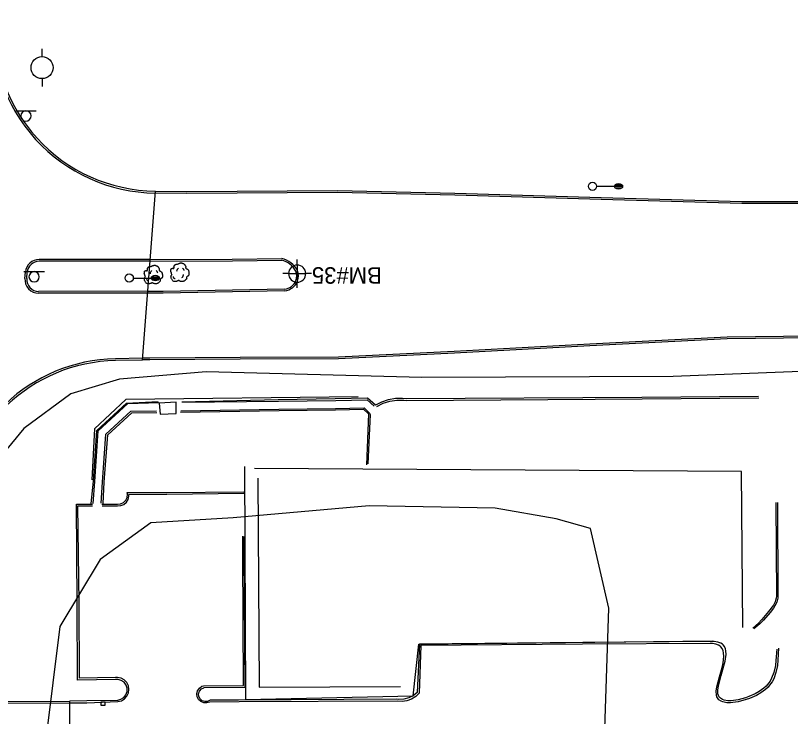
# Model space of a CAD drawing. Extents: x 2145380 to 2157287, y 139568 to 149130.
# Drawn here: x 2151088.5 to 2151370.7, y 140820 to 141075.2 of the extents above; entities that cross this region are included whole.
import ezdxf

# ---------------------------------------------------------------- set-up
doc = ezdxf.new("R2010")
doc.units = 0
for name, color, linetype in [('PR_PREVIOUSLY CONSTRUCTED', 7, 'Continuous'), ('SURV_Benchmark', 7, 'Continuous'), ('TOPO_Building', 7, 'Continuous'), ('TOPO_Curb Back', 7, 'Continuous'), ('TOPO_DRAIN Storm Sewer', 7, 'Continuous'), ('TOPO_Light Pole', 7, 'Continuous'), ('TOPO_Power Pole', 7, 'Continuous'), ('TOPO_Sign', 7, 'Continuous'), ('TOPO_Tree', 7, 'Continuous')]:
    doc.layers.add(name, color=color, linetype=linetype)

# ---------------------------------------------------------------- blocks, each defined once
blk = doc.blocks.new('LP')
at = {"layer": 'TOPO_Light Pole'}
blk.add_line((3.81, 0), (20.32, 0), dxfattribs=at)
for points in [[(20.32, 0), (27.94, 0)], [(20.32, 0), (23.5, 0)], [(20.83, 1.27), (27.43, 1.27)], [(20.83, 1.27), (23.5, 1.27)], [(23.71, 1.27), (27.43, 1.27)], [(23.71, 0), (27.94, 0)], [(20.83, -1.27), (27.43, -1.27)], [(20.83, -1.27), (23.5, -1.27)], [(23.71, -1.27), (27.43, -1.27)]]:
    blk.add_lwpolyline(points, dxfattribs=at)
blk.add_circle((0, 0), 3.81, dxfattribs=at)
blk.add_ellipse((24.13, 0), major_axis=(3.81, 0), ratio=0.666667, dxfattribs=at)
blk = doc.blocks.new('TREE')
at = {"layer": 'TOPO_Tree'}
for points in [[(-14.1, -0.4), (-14.2, 0.5), (-14.4, 1.4), (-14.6, 2.3), (-14.8, 3.2), (-15.5, 4), (-15.7, 4.9), (-15.8, 5.6), (-15.7, 6.3), (-15.7, 7), (-15.6, 7.9), (-15.7, 8.8), (-15.1, 9.7), (-14.6, 10.4), (-13.8, 10.5), (-13, 10.7), (-12.2, 11), (-11.1, 10), (-10.4, 10.7), (-9.4, 11.7), (-10.3, 13.3), (-9.8, 14.4), (-9.6, 15.1), (-9.3, 15.9), (-8.8, 16.5), (-8.2, 17.3), (-7.5, 17.7), (-6.7, 18.1), (-6.1, 18.4), (-5.6, 18.6), (-5.1, 18.7), (-4.5, 18.7), (-4, 18.5), (-3.5, 18.1)], [(-3.5, 17.6), (-3.1, 18.3), (-2.6, 18.8), (-1.9, 19.2), (-1, 19.7), (-0.2, 20), (0.7, 20.2), (1.6, 20.5), (2.5, 20.8), (3.4, 20.8), (4.1, 20.7), (4.8, 20.5), (5.5, 20.2), (6.4, 19.9), (7.3, 19.7), (8.2, 19.2), (9.4, 18.4), (10, 17.2), (10.8, 16), (11.2, 15.3), (11.6, 14.6), (11.9, 13.9), (12.2, 13.1), (11.4, 12), (11.9, 11.2), (12, 11), (12.2, 10.9), (12.4, 10.7), (12.9, 10.4), (13.5, 10), (14, 9.7), (14.7, 9.2), (15.4, 8.7), (16.1, 8.1), (16.7, 7.5), (16.9, 6.7), (17.1, 6), (17.6, 4.4), (17.7, 2.8), (17.7, 1.2), (17.7, -0.2), (17.8, -2.2), (16.6, -3), (15.5, -3.8), (14.3, -4.6), (13.2, -5.3)], [(13.2, -5.3), (13.3, -5.8), (13.4, -6.3), (13.4, -6.7), (13.8, -8.5), (12.2, -10), (10.8, -11.5), (10, -12.3), (9.1, -12.8), (8.2, -13.1), (6, -13.8), (3.3, -13.6), (1.3, -13.1), (0.5, -12.9), (-0.1, -11.4), (-0.8, -11.5), (-2, -11.6), (-3.3, -12.8), (-4.5, -13.1), (-6.1, -13.5), (-7.8, -14), (-9.3, -13.6), (-11.4, -13.1), (-12.8, -11.4), (-14.1, -9.4), (-15.3, -7.3), (-15.6, -5.1), (-15.1, -3), (-14.9, -1.9), (-13.9, -0.8), (-13.5, 0.1)], [(-4.2, 5.1), (-4.5, 6.1), (-4.3, 7.2), (-3.8, 8.2), (-3.3, 9.3), (-2.7, 10.3), (-1.6, 11)], [(5.9, 11.2), (6.5, 10.7), (7, 10.2), (7.4, 9.5), (7.9, 8.6), (8.3, 7.6), (8.5, 6.6)], [(-11.4, -4.5), (-11.5, -5.4), (-11, -6.3), (-10.1, -7.2), (-9.3, -8), (-8.5, -8.3), (-7.7, -8.1)], [(4.8, -6.3), (5.7, -5.7), (6.3, -4.9), (6.8, -3.9), (7.4, -2.8), (7.6, -1.7), (7.5, -0.6)]]:
    blk.add_open_spline(points, degree=3, dxfattribs=at)
blk = doc.blocks.new('POWPOL')
at = {"layer": 'TOPO_Power Pole'}
for p, q in [((0, 10.16), (0, 17.34)), ((0, -10.16), (0, -17.34))]:
    blk.add_line(p, q, dxfattribs=at)
blk.add_circle((0, 0), 10.16, dxfattribs=at)
blk = doc.blocks.new('BM')
at = {"layer": 'SURV_Benchmark'}
for p, q in [((0, 2.49), (0, 4.15)), ((-2.49, 0), (-4.16, 0)), ((4.16, 0), (2.49, 0)), ((0, -4.16), (0, -2.49))]:
    blk.add_line(p, q, dxfattribs=at)
for points in [[(0, 2.49), (0, 2.49), (0, 0), (2.49, 0), (2.49, 0), (2.49, 0)], [(0, 2.49), (0, 2.49), (0, 0), (2.49, 0), (2.49, 0), (2.49, 0), (2.49, 0)], [(-2.5, 0), (-2.49, 0), (0, 0), (0, -2.49), (0, -2.49)], [(-2.5, 0), (-2.49, 0), (0, 0), (0, -2.49), (0, -2.49)]]:
    blk.add_lwpolyline(points, dxfattribs=at)
for start, end in [(90.0638, 180.0068), (0.0638, 90.0068), (0.0638, 90.0068), (180.0638, 270.0068), (180.0638, 270.0068), (269.9472, 359.9927)]:
    blk.add_arc((0, 0), 2.5, start, end, dxfattribs=at)

msp = doc.modelspace()

# ---------------------------------------------------------------- linework, layer by layer
at = {"layer": 'PR_PREVIOUSLY CONSTRUCTED'}
for p, q in [((2151134.75, 140949.81), (2151139.52, 141011.28)), ((2151137.59, 140986.45), (2151097.08, 140986.42)), ((2151137.54, 140985.78), (2151097.08, 140985.75)), ((2151091.92, 140979.52), (2151092.1, 140981.8)), ((2151092.59, 140979.47), (2151092.76, 140981.75)), ((2151136.69, 140974.83), (2151096.91, 140974.8)), ((2151136.64, 140974.16), (2151096.91, 140974.13)), ((2151134.8, 140950.48), (2151124.9, 140950.28)), ((2151134.75, 140949.81), (2151124.92, 140949.61)), ((2151082.56, 140825.52), (2151108.13, 140825.61)), ((2151108.13, 140825.61), (2151108.26, 140792.3)), ((2151082.56, 140824.86), (2151108.13, 140824.94))]:
    msp.add_line(p, q, dxfattribs=at)
for centre, radius, start, end in [((2151140.12, 141070.61), 60, 175.5629, 269.2782), ((2151140.12, 141070.61), 59.33, 175.5629, 269.2782), ((2151097.08, 140981.42), 5, 90.0433, 175.5629), ((2151097.08, 140981.42), 4.33, 90.0433, 175.5629), ((2151096.91, 140979.13), 5, 175.5629, 270.0433), ((2151096.91, 140979.13), 4.33, 175.5629, 270.0433), ((2151126.13, 140890.29), 60, 91.1719, 175.5629), ((2151126.13, 140890.29), 59.33, 91.1719, 175.5629)]:
    msp.add_arc(centre, radius, start, end, dxfattribs=at)
at = {"layer": 'TOPO_Building'}
msp.add_lwpolyline([(2151353.37, 140852.4), (2151352.9, 140909.27), (2151175.52, 140910.29)], dxfattribs=at)
at = {"layer": 'TOPO_Curb Back'}
for points in [[(2151436.58, 141006.88), (2151405.76, 141006.81), (2151353, 141006.78), (2151301.78, 141008.26), (2151248.44, 141009.87), (2151205.73, 141010.82), (2151150.84, 141010.47), (2151139.48, 141010.61)], [(2151436.59, 141007.48), (2151405.76, 141007.41), (2151353.01, 141007.38), (2151301.79, 141008.86), (2151248.45, 141010.47), (2151205.74, 141011.42), (2151150.84, 141011.07), (2151139.64, 141011.21)], [(2151137.54, 140985.85), (2151167.46, 140985.9), (2151185.45, 140986.16)], [(2151137.63, 140986.45), (2151167.45, 140986.5), (2151185.51, 140986.76)], [(2151186.48, 140975.61), (2151142.23, 140974.76), (2151136.68, 140974.76)], [(2151186.49, 140975.01), (2151142.23, 140974.16), (2151136.86, 140974.16)], [(2151445.05, 140959.04), (2151399.02, 140958.75), (2151347.72, 140958.08), (2151297.64, 140955.55), (2151248.29, 140952.92), (2151206.14, 140950.87), (2151170.3, 140950.73), (2151137.43, 140950.53), (2151134.82, 140950.48)], [(2151445.06, 140958.44), (2151399.03, 140958.15), (2151347.74, 140957.48), (2151297.67, 140954.95), (2151248.32, 140952.32), (2151206.16, 140950.27), (2151170.31, 140950.13), (2151137.43, 140949.93), (2151134.9, 140949.88)], [(2151213.33, 140936.4), (2151128.71, 140935.46), (2151117.21, 140924.72), (2151116.23, 140906.21)], [(2151149.01, 140934.59), (2151184.13, 140935.47), (2151204.89, 140935.75), (2151216.74, 140935.98), (2151219.56, 140933.51)], [(2151149.3, 140934.5), (2151184.28, 140934.82), (2151205.16, 140935.06), (2151216.53, 140935.3), (2151219.06, 140933.02)], [(2151219.67, 140933.45), (2151221.95, 140934.63), (2151224.38, 140935.44), (2151226.91, 140935.86), (2151229.48, 140935.88), (2151230.76, 140935.74), (2151316.64, 140936.33), (2151359.11, 140936.67)], [(2151220.05, 140932.91), (2151222.35, 140934.05), (2151224.81, 140934.82), (2151227.35, 140935.2), (2151229.92, 140935.18), (2151230.9, 140935.07), (2151316.75, 140935.65), (2151359.21, 140936.02)], [(2151116.1, 140897.58), (2151116.84, 140905.7), (2151118.12, 140924.11), (2151128.94, 140934.15), (2151140.5, 140934.65)], [(2151116.79, 140897.59), (2151117.41, 140905.62), (2151118.61, 140924.05), (2151129.43, 140933.98), (2151140.65, 140934.4)], [(2151140.82, 140934.04), (2151141.13, 140930.13), (2151147, 140930.39), (2151147.01, 140934.41), (2151140.82, 140934.04)], [(2151148.66, 140931.35), (2151184.45, 140931.96), (2151205.04, 140932.21), (2151215.45, 140932.42), (2151217.39, 140930.5), (2151217.71, 140929.93), (2151216.81, 140911.96)], [(2151119.68, 140897.68), (2151120.17, 140905.29), (2151121.36, 140922.8), (2151130.49, 140931.18), (2151139.87, 140931.34)], [(2151120.36, 140897.54), (2151120.76, 140905.32), (2151122.06, 140922.55), (2151130.82, 140930.62), (2151139.97, 140930.66)], [(2151148.59, 140930.79), (2151184.53, 140931.41), (2151205, 140931.65), (2151215.2, 140931.89), (2151217.04, 140930.17), (2151216.28, 140911.63)], [(2151171.9, 140911.06), (2151172.3, 140826.18), (2151233.29, 140827.53), (2151235.39, 140846.33), (2151342.17, 140847.55)], [(2151176.77, 140906.78), (2151177.26, 140830.68), (2151228.7, 140830.96)], [(2151119.96, 140897.34), (2151125.62, 140897.36), (2151126.77, 140897.46), (2151127.82, 140897.95), (2151128.65, 140898.76), (2151129.15, 140899.81), (2151129.26, 140900.96), (2151129.17, 140901.56), (2151143.56, 140901.61), (2151171.7, 140901.82)], [(2151120, 140896.74), (2151125.6, 140896.76), (2151126.81, 140896.8), (2151127.94, 140897.23), (2151128.88, 140898), (2151129.51, 140899.04), (2151129.78, 140900.22), (2151129.76, 140900.8), (2151143.55, 140900.95), (2151171.69, 140901.34)], [(2151108.13, 140824.96), (2151114.51, 140825.01), (2151125.75, 140825.42), (2151127.04, 140825.73), (2151128.19, 140826.4), (2151129.08, 140827.38), (2151129.64, 140828.58), (2151129.82, 140829.89), (2151129.6, 140831.19), (2151129, 140832.38), (2151128.08, 140833.33), (2151126.92, 140833.96), (2151125.62, 140834.23), (2151124.89, 140834.2), (2151111.79, 140833.91), (2151111.65, 140861.35), (2151111.18, 140896.68), (2151116.55, 140896.68)], [(2151108.28, 140825.72), (2151114.47, 140825.8), (2151125.71, 140825.98), (2151126.9, 140826.29), (2151127.93, 140826.96), (2151128.69, 140827.92), (2151129.1, 140829.07), (2151129.12, 140830.3), (2151128.75, 140831.47), (2151128.03, 140832.46), (2151127.02, 140833.17), (2151125.85, 140833.52), (2151124.95, 140833.52), (2151111.09, 140833.19), (2151110.94, 140861.13), (2151110.75, 140897.34), (2151116.49, 140897.33)], [(2151365.37, 140897.99), (2151365.61, 140863.77), (2151365.56, 140863.08), (2151365.18, 140861.77), (2151364.51, 140860.54), (2151362.74, 140858.25), (2151360.34, 140855.38), (2151359.1, 140854.03), (2151357.03, 140852.15)], [(2151366.02, 140897.99), (2151366.15, 140863.82), (2151366.1, 140863.08), (2151365.74, 140861.68), (2151365.09, 140860.35), (2151364.56, 140859.51), (2151363.35, 140857.91), (2151360.93, 140855.06), (2151359.62, 140853.76), (2151357.39, 140851.99)], [(2151366.39, 140844.85), (2151366.17, 140840.51), (2151365.96, 140838.59), (2151365.45, 140836), (2151364.62, 140833.71), (2151364.06, 140832.66), (2151363.13, 140831.36), (2151362.58, 140830.75), (2151361.64, 140829.88), (2151359.96, 140828.65), (2151358.32, 140827.71), (2151355.86, 140826.61), (2151354.57, 140826.14), (2151351.63, 140825.34), (2151349.74, 140825.06), (2151348.84, 140825), (2151347.58, 140825.02), (2151346.11, 140825.3), (2151345.48, 140825.55), (2151344.69, 140826.07), (2151344.12, 140826.78), (2151343.93, 140827.22), (2151343.78, 140827.81), (2151343.73, 140829.2), (2151343.95, 140830.81), (2151344.87, 140834.46), (2151345.82, 140837.88), (2151346.19, 140839.55), (2151346.47, 140841.88), (2151346.39, 140843.25), (2151346.25, 140843.88), (2151345.89, 140844.71), (2151345.41, 140845.34), (2151345.11, 140845.61), (2151344.57, 140845.96), (2151343.56, 140846.34), (2151342.28, 140846.53), (2151341.54, 140846.55), (2151295.02, 140846.33), (2151236.16, 140845.89), (2151235.48, 140828.52), (2151234.23, 140827.25), (2151232.74, 140826.29), (2151231.07, 140825.68), (2151229.3, 140825.46), (2151227.56, 140825.64), (2151169.89, 140825.33), (2151159.23, 140825.28), (2151158.15, 140824.94), (2151157.03, 140824.99), (2151155.99, 140825.42), (2151155.17, 140826.19), (2151154.66, 140827.2), (2151154.54, 140828.32), (2151154.81, 140829.41), (2151155.45, 140830.34), (2151156.37, 140831), (2151157, 140831.22), (2151171.49, 140831.25), (2151171.25, 140879.16), (2151171.3, 140885.7)], [(2151365.73, 140844.51), (2151365.46, 140840.38), (2151365.23, 140838.55), (2151364.71, 140836.09), (2151363.88, 140833.91), (2151363.33, 140832.92), (2151362.42, 140831.69), (2151361.89, 140831.11), (2151360.98, 140830.28), (2151359.36, 140829.12), (2151357.84, 140828.26), (2151355.57, 140827.25), (2151354.37, 140826.81), (2151351.66, 140826.08), (2151349.1, 140825.74), (2151347.93, 140825.76), (2151346.56, 140825.99), (2151345.98, 140826.2), (2151345.24, 140826.66), (2151344.69, 140827.28), (2151344.5, 140827.67), (2151344.34, 140828.24), (2151344.28, 140829.62), (2151344.5, 140831.23), (2151345.49, 140834.93), (2151346.52, 140838.43), (2151346.93, 140840.14), (2151347.26, 140842.54), (2151347.21, 140843.95), (2151347.07, 140844.59), (2151346.72, 140845.45), (2151346.23, 140846.1), (2151345.92, 140846.38), (2151345.37, 140846.74), (2151344.32, 140847.13), (2151343, 140847.33), (2151342.23, 140847.35), (2151295.16, 140847.01), (2151235.57, 140846.32), (2151234.82, 140828.75), (2151233.37, 140827.59), (2151231.71, 140826.76), (2151229.91, 140826.31), (2151228.06, 140826.25), (2151227.22, 140826.36), (2151169.68, 140825.99), (2151159.36, 140825.94), (2151158.45, 140825.49), (2151157.44, 140825.42), (2151156.48, 140825.74), (2151155.71, 140826.4), (2151155.26, 140827.31), (2151155.19, 140828.32), (2151155.52, 140829.29), (2151156.18, 140830.05), (2151157.09, 140830.5), (2151157.21, 140830.53), (2151172.16, 140830.71), (2151171.8, 140879.27), (2151171.8, 140885.53)]]:
    msp.add_lwpolyline(points, dxfattribs=at)
for centre, radius, start, end in [((2151183.48, 140978.27), 8.13, 28.9945, 76.0043), ((2151183.48, 140978.27), 8.73, 28.7852, 76.5263), ((2151186.31, 140980.4), 4.65, 338.499, 22.8398), ((2151186.31, 140980.4), 5.25, 338.4428, 23.1983), ((2151185.97, 140980.63), 5.05, 275.4932, 337.5457), ((2151185.97, 140980.63), 5.65, 275.4932, 337.5957)]:
    msp.add_arc(centre, radius, start, end, dxfattribs=at)
at = {"layer": 'TOPO_DRAIN Storm Sewer'}
msp.add_lwpolyline([(2151121.09, 140825.17), (2151119.59, 140825.17), (2151119.59, 140824.17), (2151121.09, 140824.17)], close=True, dxfattribs=at)
at = {"layer": 'TOPO_Sign'}
for points in [[(2151088.55, 141040.55), (2151096.04, 141040.56)], [(2151092.3, 141040.55), (2151092.3, 141040.55)], [(2151090.43, 141038.68), (2151090.43, 141038.68)], [(2151094.16, 141038.68), (2151094.16, 141038.68)], [(2151092.3, 141036.81), (2151092.3, 141036.81)], [(2151091.5, 140981.99), (2151098.99, 140981.99)], [(2151095.25, 140981.99), (2151095.25, 140981.99)], [(2151093.38, 140980.12), (2151093.38, 140980.12)], [(2151095.25, 140978.25), (2151095.25, 140978.25)], [(2151097.12, 140980.12), (2151097.12, 140980.12)]]:
    msp.add_lwpolyline(points, dxfattribs=at)
for centre, start, end in [((2151092.3, 141038.68), 90, 180), ((2151092.3, 141038.68), 360, 90), ((2151092.3, 141038.68), 180, 270), ((2151092.3, 141038.68), 270, 0), ((2151095.25, 140980.12), 90, 180), ((2151095.25, 140980.12), 360, 90), ((2151095.25, 140980.12), 180, 270), ((2151095.25, 140980.12), 270, 0)]:
    msp.add_arc(centre, 1.87, start, end, dxfattribs=at)
at = {"layer": 'TOPO_Tree'}
for points in [[(2151445.18, 140947.89), (2151420.82, 140947.46), (2151328.06, 140943.84), (2151236.48, 140943.46), (2151157.97, 140945.53), (2151126.34, 140942.83), (2151108.69, 140937.48), (2151091.58, 140924.88), (2151080.67, 140911.9), (2151069.39, 140864.17), (2151059.56, 140742.95), (2151055.53, 140643.54)], [(2151297.26, 140658.82), (2151298.51, 140707.92), (2151300.37, 140731.45), (2151304.63, 140859.51), (2151297.85, 140888.43), (2151285.41, 140892.01), (2151263.23, 140895.91), (2151217.25, 140896.74), (2151167.82, 140892.4), (2151137.82, 140890.55), (2151119.33, 140877.19), (2151104.66, 140852.83), (2151097, 140791.22), (2151098.19, 140770.62), (2151101.62, 140753.6), (2151113.78, 140728.81), (2151117.8, 140715.84), (2151114.46, 140703.99), (2151104.19, 140697.2), (2151102.22, 140689.73), (2151099, 140676.87), (2151096.99, 140653.6)]]:
    msp.add_lwpolyline(points, dxfattribs=at)

# ---------------------------------------------------------------- block references
at = {"layer": 'SURV_Benchmark', "xscale": 1.2499999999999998, "yscale": 1.25}
msp.add_blockref('BM', (2151191.09, 140981.27), dxfattribs=at)
at = {"layer": 'TOPO_Light Pole', "xscale": 0.39370000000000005, "yscale": 0.3937000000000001}
for p in [(2151298.62, 141013.06), (2151129.9, 140979.65)]:
    msp.add_blockref('LP', p, dxfattribs=at)
at = {"layer": 'TOPO_Power Pole', "xscale": 0.39370000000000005, "yscale": 0.3937000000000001}
msp.add_blockref('POWPOL', (2151098.15, 141056.27), dxfattribs=at)
at = {"layer": 'TOPO_Tree', "xscale": 0.19685000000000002, "yscale": 0.19685000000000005}
for p in [(2151138.5, 140980.24), (2151148.16, 140981.07)]:
    msp.add_blockref('TREE', p, dxfattribs=at)

# ---------------------------------------------------------------- texts
at = {"layer": 'SURV_Benchmark'}
msp.add_text('BM#35', height=6, rotation=180, dxfattribs=at).set_placement((2151221.87, 140983.6))

doc.saveas('drawing.dxf')
